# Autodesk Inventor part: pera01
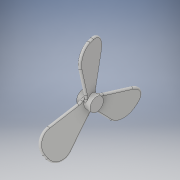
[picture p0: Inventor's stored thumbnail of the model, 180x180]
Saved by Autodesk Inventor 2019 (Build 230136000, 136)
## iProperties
Created: 2020-08
Part Number: pera01
Material: 一般
Document SubType Name: Modeling
Designer: kikut
Density: 1 g/cm^3
Appearance: 既定
Author: kikut
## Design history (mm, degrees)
sketch "スケッチ3"
  geometry: L1 (0.005, -0.009)-(-0.001, 0.01); L2 (-0.001, 0.01)-(-0.005, 0.009); L3 (-0.005, 0.009)-(0.001, -0.01); L4 (0.001, -0.01)-(0.005, -0.009); L5 (0.005, -0.009)-(-0.005, 0.009); L6 (-0.001, 0.01)-(0.001, -0.01); L7 (0, -0.014)-(0, 0.014) reference; 3 further points
  constraints: 12 end point, 3 midpoint, 2 parallel, 1 coincident, 1 perpendicular
  dimensions: "d8" = 0.02 distance of L1.start L1.end; "d9" = 15 deg angle of L7 L1; "d19" = 0.004 distance of L3.end L1.start
extrude "押し出し1" new body sketch "スケッチ3" distance "d10" = 0.079; taper "d11" = 0 deg
sketch "スケッチ6"
  geometry: L1 (-0.02, 0)-(-0.02, 0.079) reference; L2 (-0.02, 0.01)-(-0.04, 0.079); L3 (-0.04, 0.079)-(0.02, 0.079); L4 (0.02, 0.079)-(0, 0.01); L5 (0, 0)-(0, 0.079) reference; L6 (-0.02, 0.01)-(0, 0.01); L7 (-0.02, 0)-(0, 0) reference; 1 further point
  constraints: 8 end point, 2 perpendicular, 2 point on line
  dimensions: "d20" = 0.06 distance of L2.end L3.end; "d21" = 0.01 distance between parallel lines of L7 L6; "d22" = 0.02 distance from line of L1 L2.end
extrude "押し出し3" join sketch "スケッチ6" distance "d23" = 0.004; taper "d24" = 0 deg
fillet "フィレット2" dims "d25" = 0.02
fillet "フィレット3" dims "d26" = 0.02
pattern_circular "円形状パターン2" dims "d28" = 360 deg
sketch "スケッチ7"
  geometry: L1 (-0.008, -0.005)-(0, 0) reference; C1 r 0.01 at (0, 0)
  constraints: 1 centre point, 1 coincident
  dimensions: "d30" = 0.02 diameter of C1
extrude "押し出し4" join sketch "スケッチ7" stored distance "d31" = 0.02; taper "d32" = 0 deg
fillet "フィレット5" dims "d34" = 0.002
node "ソリッド1"
